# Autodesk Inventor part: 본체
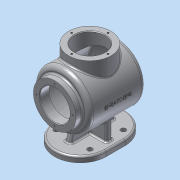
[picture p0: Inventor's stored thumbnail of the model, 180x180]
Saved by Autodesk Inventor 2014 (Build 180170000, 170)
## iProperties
Created: 2023-01
Part Number: 본체
Material: 알루미늄 6061
Document SubType Name: Modeling
Designer: dg
Density: 2.71 g/cm^3
Appearance: 알루미늄 - 평지
Mass: 1041.95 g
Surface Area: 1156.58 cm^2
Volume: 384.484 cm^3
Author: dg
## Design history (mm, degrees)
sketch "스케치1"
  geometry: L1 (0, 0)-(122, 0); L2 (0, 27)-(0, 38); L3 (0, 38)-(12, 38); L4 (12, 38)-(12, 50); L5 (12, 50)-(111.087, 50); L6 (0, 27)-(17, 27); L7 (17, 27)-(17, 45); L8 (17, 45)-(107.374, 45); A1 r 120 centre (2, 0) between (122, 0) and (111.087, 50); A2 r 110 centre (7, 0) between (117, 0) and (107.374, 45)
  constraints: 16 end point, 4 parallel, 4 point on circle, 3 perpendicular, 2 centre point, 2 horizontal alignment, 1 horizontal, 1 point on line, 1 vertical alignment
  dimensions: "d0" = 122 distance of L1.start L1.end; "d1" = 54 diameter of L6 L1; "d2" = 17 distance of L2.start L6.end; "d3" = 5 distance of L1.end A2.start; "d4" = 120 radius of A1; "d5" = 110 distance from line of L1.end L4; "d6" = 76 diameter of L3 L1; "d7" = 100 diameter of L5 L1; "d8" = 90 diameter of L8 L1; "d9" = 110 radius of A2
revolve "회전1" sketch "스케치1" stored, may be unused: angle "d10" = 90 deg
node "작업 평면1"
sketch "스케치2"
  geometry: L1 (0, 80)-(0, 46); L2 (-46, 80)-(-46, 46); L3 (46, 46)-(46, 80); A1 r 46 centre (0, 80) between (46, 80) and (-46, 80); A2 r 46 centre (0, 46) between (-46, 46) and (46, 46); 3 further points
  constraints: 8 end point, 5 point on circle, 4 tangent, 2 centre point, 1 coincident, 1 midpoint, 1 parallel, 1 vertical, 1 vertical alignment
  dimensions: "d12" = 126 dimension on A2 A1; "d13" = 92 distance between parallel lines of L3 L2
extrude "돌출1" join sketch "스케치2" distance "d14" = 10; taper "d15" = 0 deg
sketch "스케치3"
  geometry: L1 (-46, 80)-(-46, 46) reference; L2 (-35, 58)-(35, 58); L3 (35, 58)-(35, 68); L4 (35, 68)-(-35, 68); L5 (-35, 68)-(-35, 58); A1 r 46 centre (0, 80) between (46, 80) and (-46, 80) reference; 5 further points
  constraints: 8 end point, 3 midpoint, 2 parallel, 1 horizontal, 1 horizontal alignment, 1 perpendicular, 1 point on circle, 1 vertical alignment
  dimensions: "d16" = 10 distance of L2.end L3.end; "d17" = 70 distance of L3.end L4.end
extrude "돌출2" join sketch "스케치3" stored distance "d18" = 10; taper "d19" = 0 deg
sketch "스케치4"
  geometry: L1 (-46, 80)-(-46, 46) reference; L2 (-5, 103)-(5, 103); L3 (5, 103)-(5, 23); L4 (5, 23)-(-5, 23); L5 (-5, 23)-(-5, 103); A1 r 46 centre (0, 80) between (46, 80) and (-46, 80) reference; 5 further points
  constraints: 8 end point, 3 midpoint, 2 parallel, 1 horizontal, 1 horizontal alignment, 1 perpendicular, 1 point on circle, 1 vertical alignment
  dimensions: "d20" = 10 distance of L2.start L2.end; "d21" = 80 distance of L2.end L3.end
extrude "돌출3" join sketch "스케치4" stored distance "d22" = 10; taper "d23" = 0 deg
feature "면 기울기2" dims angle "d25" = 15 deg
feature "면 기울기3" dims angle "d26" = 15 deg
node "작업 평면2"
sketch "스케치5"
  geometry: C1 r 38 at (0, 63); 1 further point
  constraints: 1 centre point, 1 vertical alignment
  dimensions: "d28" = 76 diameter of C1; "d29" = 63 distance of point (0, 0) C1.centre
extrude "돌출4" join sketch "스케치5" stored distance "d30" = 10; taper "d31" = 0 deg
hole "구멍1" diameter "d34" = 54; stored, may be unused: countersink angle "d38" = 90 deg, drill point angle "d40" = 118 deg; dims "d32" = 10, "d33" = 10, "d35" = 6, "d36" = 4, "d37" = 2, "d39" = 8
sketch "스케치6"
  geometry: C1 r 27 at (0, 0) reference; 2 further points
  constraints: 1 vertical alignment
  dimensions: "d41" = 32.5 distance of C1.centre point (0, 32.5)
hole "구멍2" sketch "스케치6" at (0, 32.5) diameter "d42" = 3.242; stored, may be unused: countersink angle "d46" = 90 deg, drill point angle "d48" = 118 deg; dims "d43" = 8, "d44" = 4, "d45" = 2, "d47" = 10
sketch "스케치7"
  geometry: C1 r 38 at (0, 0) reference; 1 further point
  constraints: 1 vertical alignment
  dimensions: "d52" = 32.5 distance of C1.centre point (0, 32.5)
hole "구멍3" sketch "스케치7" at (0, 32.5) diameter "d53" = 3.242; stored, may be unused: countersink angle "d57" = 90 deg, drill point angle "d59" = 118 deg; dims "d54" = 8, "d55" = 4, "d56" = 2, "d58" = 10
chamfer "모따기1" distance "d63" = 1; stored, may be unused: second distance "d64" = 2, angle "d65" = 45 deg
fillet "모깎기1" dims "d66" = 8
sketch "스케치8"
  geometry: L1 (35, 68)-(35, 58) reference; L2 (-35, 58)-(-35, 68) reference; A1 r 46 centre (0, 80) between (46, 80) and (-46, 80) reference; 7 further points
  constraints: 3 horizontal alignment, 2 midpoint, 2 vertical alignment
  dimensions: "d67" = 60 distance of point (30, 93) point (-30, 93); "d68" = 30 horizontal distance of A1.centre point (-30, 93) (= 0.5 x d67); "d69" = 60 distance of point (30, 33) point (30, 93); "d70" = 30 vertical distance of point (35, 63) point (30, 33) (= 0.5 x d69)
hole "구멍4" sketch "스케치8" at (-30, 93), (30, 93), (30, 33), (-30, 33) diameter "d71" = 9; stored, may be unused: countersink angle "d75" = 90 deg, drill point angle "d77" = 118 deg; dims "d72" = 8, "d73" = 4, "d74" = 2, "d76" = 9
fillet "모깎기2" dims "d78" = 3
fillet "모깎기3" dims "d79" = 3
fillet "모깎기4" dims "d80" = 3
node "작업 평면3"
sketch "스케치9"
  geometry: L1 (64.456, -80)-(18.456, -80) reference; 2 further points
  constraints: 1 other
  dimensions: "d81" = 63 distance of point (1.456, 0) point (-61.544, 0); "d82" = 80 distance from line of L1 point (1.456, 0)
feature "엠보싱1" sketch "스케치9" dims "d0" = 122, "d1" = 54, "d2" = 17, "d3" = 5, "d4" = 120, "d5" = 110, "d6" = 76, "d7" = 100, "d8" = 90, "d9" = 110, "d12" = 126, "d13" = 92, "d83" = 0.5, "d84" = 0
node "솔리드1"
pattern_circular "원형 패턴1" dims angle "d50" = 360 deg
pattern_circular "원형 패턴2" dims angle "d61" = 360 deg
other parameters: "d27" = 64
